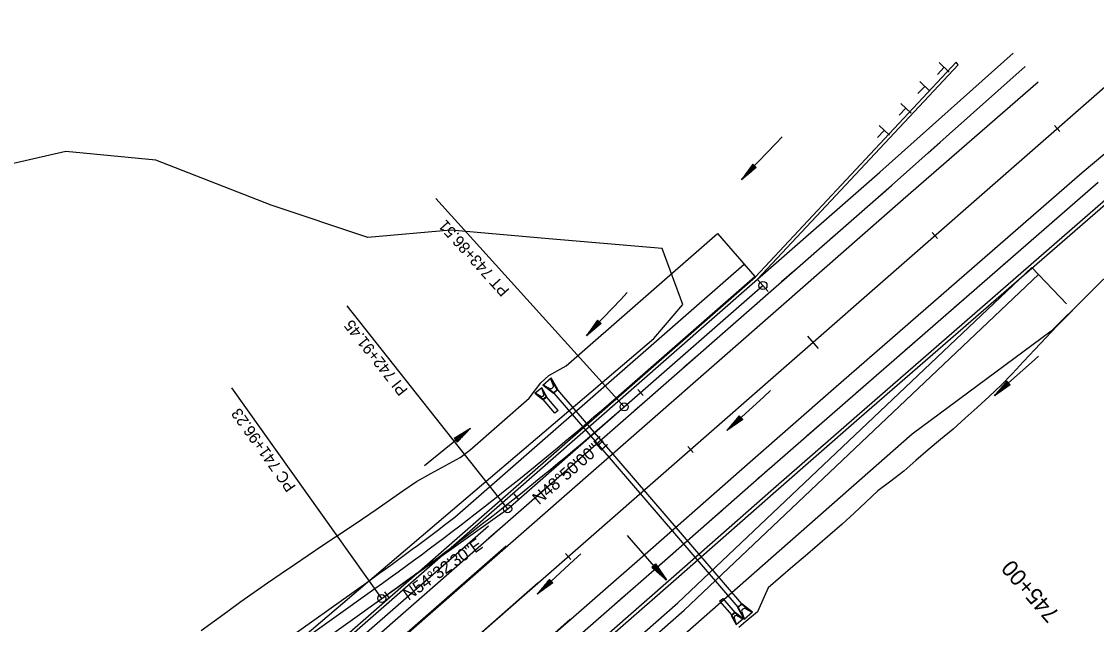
# Model space of a CAD drawing. Extents: x 1300404 to 1323571, y 234004 to 252077.
# Drawn here: x 1312081 to 1312743, y 242384 to 242755 of the extents above; entities that cross this region are included whole.
import ezdxf

# ---------------------------------------------------------------- set-up
doc = ezdxf.new("R2010")
doc.units = 0
for name, color, linetype in [('R_Barrel', 7, 'Continuous'), ('R_Const Limits', 7, 'Continuous'), ('R_Draft', 7, 'Continuous'), ('R_FES', 7, 'Continuous'), ('R_Flooplain', 7, 'Continuous'), ('R_Flow Arrows', 7, 'Continuous'), ('R_Horz Alg Annot', 7, 'Continuous'), ('R_Horz Alg Annot Leader', 7, 'Continuous'), ('R_Horz Alg Major Ticks', 7, 'Continuous'), ('R_Horz Alg Minor Ticks', 7, 'Continuous'), ('R_Horz Alg Station Annot', 7, 'Continuous'), ('R_Horz Alg Tangents', 7, 'Continuous'), ('R_Horz Alg Tangents Text', 7, 'Continuous'), ('R_Lane Edge', 7, 'Continuous'), ('R_Pipe Culvert', 7, 'Continuous'), ('R_Proposed', 7, 'Continuous'), ('R_Shoulder', 7, 'Continuous'), ('R_Temp Barrier Wall', 7, 'Continuous'), ('R_Temp Travel Lane', 7, 'Continuous'), ('R_Temp Travel Stripe', 7, 'Continuous')]:
    doc.layers.add(name, color=color, linetype=linetype)

msp = doc.modelspace()

# ---------------------------------------------------------------- linework, layer by layer
at = {"layer": 'R_Barrel'}
for p, q in [((1312648.96, 242726.58), (1312644.8, 242722.26)), ((1312645.87, 242729.55), (1312652.07, 242723.59)), ((1312636.94, 242714.85), (1312632.78, 242710.53)), ((1312633.85, 242717.82), (1312640.05, 242711.85)), ((1312625.4, 242701.39), (1312621.24, 242697.07)), ((1312622.31, 242704.36), (1312628.51, 242698.39)), ((1312612.04, 242687.8), (1312607.88, 242683.48)), ((1312608.96, 242690.77), (1312615.16, 242684.8))]:
    msp.add_line(p, q, dxfattribs=at)
at = {"layer": 'R_Const Limits'}
for p, q in [((1312416.15, 242542.82), (1312509.35, 242624.32)), ((1312509.35, 242624.32), (1312532.39, 242597.97)), ((1312509.35, 242624.32), (1312532.39, 242597.97)), ((1312724.16, 242581), (1312702.84, 242603.5)), ((1312724.16, 242581), (1312702.84, 242603.5)), ((1312405.62, 242536.92), (1312416.15, 242542.82)), ((1312400.61, 242532.53), (1312405.62, 242536.92)), ((1312393.42, 242522.95), (1312400.61, 242532.53)), ((1312356.89, 242491), (1312393.42, 242522.95))]:
    msp.add_line(p, q, dxfattribs=at)
for points in [[(1312727.96, 242576.99), (1312718.46, 242567.48), (1312711.52, 242560.23), (1312704.65, 242552.9), (1312697.81, 242545.52), (1312690.96, 242538.17), (1312683.93, 242531.01), (1312676.67, 242524.13), (1312669.32, 242517.34), (1312661.88, 242510.66), (1312654.39, 242504.03), (1312646.73, 242497.6), (1312639.1, 242491.13), (1312631.52, 242484.61), (1312623.99, 242478.02), (1312616.06, 242471.9), (1312607.99, 242465.94), (1312600.72, 242459.07), (1312593.47, 242452.16), (1312586.08, 242445.42), (1312578.49, 242438.92), (1312570.91, 242432.39), (1312563.35, 242425.84), (1312555.75, 242419.34), (1312548.13, 242412.87), (1312540.54, 242406.35), (1312540.54, 242406.35), (1312533.94, 242391.51), (1312526.73, 242385.56), (1312522.45, 242381.96)], [(1312191.55, 242380.1), (1312199.69, 242385.98), (1312207.81, 242391.89), (1312215.93, 242397.8), (1312224.09, 242403.66), (1312232.4, 242409.34), (1312240.65, 242415.1), (1312249.02, 242420.72), (1312257.34, 242426.4), (1312265.68, 242432.06), (1312274.12, 242437.59), (1312282.51, 242443.19), (1312290.85, 242448.84), (1312299.17, 242454.52), (1312307.48, 242460.2), (1312315.72, 242465.98), (1312324.03, 242471.66), (1312332.93, 242476.67), (1312341.95, 242481.55), (1312350.86, 242486.56), (1312356.89, 242491)]]:
    msp.add_lwpolyline(points, dxfattribs=at)
at = {"layer": 'R_Draft'}
for p, q in [((1308396.96, 238971.92), (1312368.36, 242444.53)), ((1308407.83, 238959.5), (1312379.22, 242432.11)), ((1308447.32, 238914.33), (1312418.71, 242386.94))]:
    msp.add_line(p, q, dxfattribs=at)
at = {"layer": 'R_FES'}
for p, q in [((1312401.86, 242531.06), (1312406.88, 242535.46)), ((1312408.21, 242531.11), (1312406.62, 242535.23)), ((1312410.71, 242528.38), (1312406.62, 242535.23)), ((1312411.12, 242528.35), (1312406.88, 242535.46)), ((1312406.88, 242535.46), (1312408.21, 242531.11)), ((1312401.24, 242529.44), (1312396.97, 242525.85)), ((1312401.01, 242529.25), (1312402.47, 242525.49)), ((1312403.88, 242523.98), (1312401.01, 242529.25)), ((1312404.24, 242523.93), (1312401.24, 242529.44)), ((1312402.47, 242525.49), (1312401.24, 242529.44)), ((1312408.36, 242525.93), (1312401.86, 242531.06)), ((1312406.03, 242528.95), (1312401.86, 242531.06)), ((1312402.12, 242531.29), (1312406.03, 242528.95)), ((1312408.39, 242526.33), (1312402.12, 242531.29)), ((1312411.12, 242528.35), (1312408.36, 242525.93)), ((1312410.71, 242528.38), (1312408.39, 242526.33)), ((1312410.71, 242528.38), (1312411.12, 242528.35)), ((1312401.88, 242521.95), (1312396.97, 242525.85)), ((1312396.97, 242525.85), (1312400.62, 242524.12)), ((1312400.62, 242524.12), (1312397.19, 242526.04)), ((1312401.89, 242522.31), (1312397.19, 242526.04)), ((1312401.88, 242521.95), (1312404.24, 242523.93)), ((1312401.89, 242522.31), (1312401.88, 242521.95)), ((1312401.89, 242522.31), (1312403.88, 242523.98)), ((1312403.88, 242523.98), (1312404.24, 242523.93)), ((1312408.39, 242526.33), (1312408.36, 242525.93)), ((1312524.36, 242396.6), (1312521.59, 242394.19)), ((1312524.33, 242396.2), (1312522, 242394.16)), ((1312524.33, 242396.2), (1312524.36, 242396.6)), ((1312524.33, 242396.2), (1312530.59, 242391.23)), ((1312524.36, 242396.6), (1312530.84, 242391.45)), ((1312520.23, 242391.31), (1312517.87, 242389.32)), ((1312517.87, 242389.32), (1312520.87, 242383.81)), ((1312518.23, 242389.27), (1312517.87, 242389.32)), ((1312520.22, 242390.94), (1312518.23, 242389.27)), ((1312518.23, 242389.27), (1312521.1, 242384)), ((1312520.22, 242390.94), (1312520.23, 242391.31)), ((1312520.22, 242390.94), (1312524.92, 242387.21)), ((1312520.23, 242391.31), (1312525.15, 242387.41)), ((1312521.49, 242389.13), (1312524.92, 242387.21)), ((1312525.15, 242387.41), (1312521.49, 242389.13)), ((1312521.59, 242394.19), (1312525.82, 242387.07)), ((1312522, 242394.16), (1312521.59, 242394.19)), ((1312522, 242394.16), (1312526.08, 242387.29)), ((1312524.28, 242391.48), (1312525.82, 242387.07)), ((1312526.08, 242387.29), (1312524.28, 242391.48)), ((1312525.82, 242387.07), (1312530.84, 242391.45)), ((1312526.71, 242393.35), (1312530.59, 242391.23)), ((1312530.84, 242391.45), (1312526.71, 242393.35)), ((1312519.64, 242387.76), (1312520.87, 242383.81)), ((1312521.1, 242384), (1312519.64, 242387.76)), ((1312520.87, 242383.81), (1312525.15, 242387.41))]:
    msp.add_line(p, q, dxfattribs=at)
for centre, radius, start, end in [((1312406.66, 242530.5), 1.67, 247.94997, 21.48071), ((1312401.25, 242525.2), 1.25, 239.82319, 13.35393), ((1312520.86, 242388.05), 1.25, 59.82319, 193.35393), ((1312525.9, 242391.9), 1.67, 60.89676, 194.4275)]:
    msp.add_arc(centre, radius, start, end, dxfattribs=at)
at = {"layer": 'R_Flooplain'}
for p, q in [((1312108.08, 242674.72), (1312046.9, 242660.87)), ((1312163.47, 242669.51), (1312108.08, 242674.72)), ((1312234.67, 242641.73), (1312163.47, 242669.51)), ((1312294.17, 242621.8), (1312234.67, 242641.73)), ((1312345.21, 242626.48), (1312294.17, 242621.8)), ((1312405.43, 242621.03), (1312345.21, 242626.48)), ((1312475.3, 242615.09), (1312405.43, 242621.03)), ((1312488.09, 242580.57), (1312475.3, 242615.09)), ((1312768.17, 242617.27), (1312714.72, 242564.31)), ((1312470.12, 242559.7), (1312488.09, 242580.57)), ((1312714.72, 242564.31), (1312629.3, 242500.87)), ((1311459.52, 241700.85), (1312470.12, 242559.7)), ((1312629.3, 242500.87), (1311599.52, 241597.01))]:
    msp.add_line(p, q, dxfattribs=at)
at = {"layer": 'R_Flow Arrows'}
for p, q in [((1312531.03, 242667.02), (1312524.1, 242657.41)), ((1312533.25, 242664.94), (1312531.03, 242667.02)), ((1312533.25, 242664.94), (1312524.1, 242657.41)), ((1312435.53, 242571.07), (1312428.61, 242561.46)), ((1312437.75, 242568.99), (1312428.61, 242561.46)), ((1312437.75, 242568.99), (1312435.53, 242571.07)), ((1312687.52, 242533.5), (1312679.81, 242524.51)), ((1312689.56, 242531.24), (1312679.81, 242524.51)), ((1312689.56, 242531.24), (1312687.52, 242533.5)), ((1312522.8, 242512.19), (1312515.18, 242503.12)), ((1312524.86, 242509.95), (1312515.18, 242503.12)), ((1312524.86, 242509.95), (1312522.8, 242512.19)), ((1312347.19, 242498.31), (1312357.24, 242504.6)), ((1312349.12, 242495.96), (1312357.24, 242504.6)), ((1312347.19, 242498.31), (1312349.12, 242495.96)), ((1312471.16, 242420.97), (1312468.9, 242418.94)), ((1312468.9, 242418.94), (1312477.88, 242411.21)), ((1312471.16, 242420.97), (1312477.88, 242411.21)), ((1312405.97, 242411.53), (1312398.34, 242402.47)), ((1312408.03, 242409.29), (1312398.34, 242402.47)), ((1312408.03, 242409.29), (1312405.97, 242411.53))]:
    msp.add_line(p, q, dxfattribs=at)
for points in [[(1312549.22, 242683.88), (1312545.24, 242679.71), (1312524, 242657.51)], [(1312531.47, 242666.6), (1312528.26, 242663.17)], [(1312531.25, 242666.81), (1312529.64, 242665.1)], [(1312531.92, 242666.19), (1312527.66, 242661.65), (1312525.48, 242659.34)], [(1312532.36, 242665.77), (1312528.11, 242661.24), (1312525.93, 242658.92)], [(1312531.69, 242666.4), (1312527.44, 242661.86), (1312526.87, 242661.26)], [(1312532.58, 242665.56), (1312528.33, 242661.03), (1312527.76, 242660.42)], [(1312532.8, 242665.36), (1312529.59, 242661.93)], [(1312533.03, 242665.15), (1312531.42, 242663.43)], [(1312453.72, 242587.93), (1312449.75, 242583.76), (1312428.5, 242561.56)], [(1312436.42, 242570.24), (1312432.17, 242565.7), (1312429.99, 242563.39)], [(1312436.87, 242569.82), (1312432.61, 242565.29), (1312430.43, 242562.97)], [(1312436.2, 242570.45), (1312431.95, 242565.91), (1312431.38, 242565.31)], [(1312437.09, 242569.62), (1312432.84, 242565.08), (1312432.26, 242564.47)], [(1312435.98, 242570.66), (1312432.76, 242567.23)], [(1312437.31, 242569.41), (1312434.1, 242565.98)], [(1312435.76, 242570.86), (1312434.15, 242569.15)], [(1312437.53, 242569.2), (1312435.92, 242567.48)], [(1312707.06, 242548.78), (1312702.75, 242544.95), (1312679.72, 242524.62)], [(1312542.05, 242527.81), (1312537.81, 242523.9), (1312515.18, 242503.13)], [(1312688.34, 242532.6), (1312683.72, 242528.44), (1312681.35, 242526.31)], [(1312688.75, 242532.15), (1312684.13, 242527.98), (1312681.76, 242525.86)], [(1312688.13, 242532.82), (1312683.52, 242528.66), (1312682.9, 242528.11)], [(1312688.95, 242531.92), (1312684.33, 242527.76), (1312683.71, 242527.2)], [(1312687.93, 242533.05), (1312684.44, 242529.9)], [(1312689.15, 242531.7), (1312685.66, 242528.55)], [(1312687.73, 242533.28), (1312685.98, 242531.7)], [(1312689.36, 242531.47), (1312687.61, 242529.9)], [(1312523.63, 242511.29), (1312519.05, 242507.09), (1312516.7, 242504.95)], [(1312524.04, 242510.85), (1312519.46, 242506.64), (1312517.11, 242504.5)], [(1312523.42, 242511.52), (1312518.84, 242507.31), (1312518.23, 242506.75)], [(1312524.24, 242510.62), (1312519.66, 242506.42), (1312519.05, 242505.85)], [(1312523.22, 242511.74), (1312519.75, 242508.56)], [(1312524.45, 242510.4), (1312520.99, 242507.22)], [(1312523.01, 242511.97), (1312521.28, 242510.38)], [(1312524.65, 242510.17), (1312522.92, 242508.58)], [(1312328.9, 242481.6), (1312333.39, 242485.23), (1312357.33, 242504.48)], [(1312347.77, 242497.61), (1312352.58, 242501.56), (1312353.22, 242502.08)], [(1312347.97, 242497.37), (1312352.77, 242501.32), (1312355.24, 242503.33)], [(1312348.35, 242496.9), (1312353.16, 242500.85), (1312355.62, 242502.86)], [(1312348.55, 242496.67), (1312353.35, 242500.61), (1312353.99, 242501.14)], [(1312347.39, 242498.08), (1312349.2, 242499.57)], [(1312347.58, 242497.84), (1312351.21, 242500.83)], [(1312348.74, 242496.43), (1312352.37, 242499.42)], [(1312348.93, 242496.2), (1312350.75, 242497.69)], [(1312453.67, 242438.51), (1312457.49, 242434.19), (1312477.77, 242411.11)], [(1312425.22, 242427.15), (1312420.98, 242423.24), (1312398.35, 242402.47)], [(1312469.13, 242419.14), (1312470.7, 242417.39)], [(1312469.35, 242419.34), (1312472.49, 242415.84)], [(1312469.58, 242419.55), (1312473.73, 242414.92), (1312474.28, 242414.3)], [(1312469.81, 242419.75), (1312473.96, 242415.12), (1312476.07, 242412.75)], [(1312470.26, 242420.16), (1312474.41, 242415.53), (1312476.53, 242413.15)], [(1312470.48, 242420.36), (1312474.64, 242415.73), (1312475.19, 242415.11)], [(1312470.71, 242420.56), (1312473.85, 242417.06)], [(1312470.94, 242420.76), (1312472.51, 242419.02)], [(1312406.8, 242410.63), (1312402.21, 242406.43), (1312399.87, 242404.29)], [(1312407.21, 242410.19), (1312402.63, 242405.98), (1312400.28, 242403.84)], [(1312406.59, 242410.86), (1312402.01, 242406.66), (1312401.4, 242406.09)], [(1312407.41, 242409.96), (1312402.83, 242405.76), (1312402.22, 242405.2)], [(1312406.38, 242411.08), (1312402.92, 242407.9)], [(1312407.62, 242409.74), (1312404.15, 242406.56)], [(1312406.18, 242411.31), (1312404.45, 242409.72)], [(1312407.82, 242409.51), (1312406.09, 242407.93)]]:
    msp.add_lwpolyline(points, dxfattribs=at)
at = {"layer": 'R_Horz Alg Annot Leader'}
for points in [[(1312451.89, 242517.62), (1312335.87, 242645.95)], [(1312451.89, 242517.62), (1312335.87, 242645.95)], [(1312378.37, 242457.27), (1312281.46, 242579.92)], [(1312378.37, 242457.27), (1312281.46, 242579.92)], [(1312302.65, 242399.71), (1312210.36, 242529.29)], [(1312302.65, 242399.71), (1312210.36, 242529.29)], [(1312380.21, 242454.94), (1312379.13, 242456.31)], [(1312380.21, 242454.94), (1312379.13, 242456.31)]]:
    msp.add_lwpolyline(points, dxfattribs=at)
at = {"layer": 'R_Horz Alg Major Ticks'}
for points in [[(1312534.04, 242596.09), (1312540.62, 242588.56)], [(1312534.04, 242596.09), (1312540.62, 242588.56)], [(1312564.67, 242561.06), (1312571.25, 242553.53)], [(1312564.67, 242561.06), (1312571.25, 242553.53)]]:
    msp.add_lwpolyline(points, dxfattribs=at)
at = {"layer": 'R_Horz Alg Minor Ticks'}
for points in [[(1312716.88, 242690.83), (1312720.17, 242687.06)], [(1312716.88, 242690.83), (1312720.17, 242687.06)], [(1312641.6, 242625), (1312644.89, 242621.24)], [(1312641.6, 242625), (1312644.89, 242621.24)], [(1312460.4, 242528.38), (1312463.69, 242524.62)], [(1312460.4, 242528.38), (1312463.69, 242524.62)], [(1312491.04, 242493.35), (1312494.33, 242489.59)], [(1312491.04, 242493.35), (1312494.33, 242489.59)], [(1312383.94, 242464.12), (1312387.06, 242460.22)], [(1312383.94, 242464.12), (1312387.06, 242460.22)], [(1312415.76, 242427.53), (1312419.05, 242423.76)], [(1312415.76, 242427.53), (1312419.05, 242423.76)], [(1312304.27, 242403.93), (1312307.18, 242399.86)], [(1312304.27, 242403.93), (1312307.18, 242399.86)]]:
    msp.add_lwpolyline(points, dxfattribs=at)
at = {"layer": 'R_Horz Alg Tangents'}
for p, q in [((1312380.21, 242454.94), (1312451.89, 242517.62)), ((1312380.21, 242454.94), (1312451.89, 242517.62)), ((1312302.65, 242399.71), (1312380.21, 242454.94)), ((1312302.65, 242399.71), (1312380.21, 242454.94))]:
    msp.add_line(p, q, dxfattribs=at)
at = {"layer": 'R_Lane Edge'}
for p, q in [((1312484.9, 242396.99), (1312702.84, 242603.5)), ((1312446.95, 242523.27), (1312532.39, 242597.97)), ((1311865.98, 242097.91), (1312298.3, 242405.81)), ((1312070.61, 242034.74), (1312484.9, 242396.99))]:
    msp.add_line(p, q, dxfattribs=at)
msp.add_arc((1311194.72, 243955.36), 1902.36, 305.45833, 311.16667, dxfattribs=at)
at = {"layer": 'R_Pipe Culvert'}
for p, q in [((1312410.87, 242528.13), (1312524.11, 242396.39)), ((1312409.19, 242513.84), (1312402.1, 242522.13)), ((1312411.21, 242515.32), (1312404.01, 242523.74)), ((1312408.61, 242526.15), (1312521.85, 242394.41)), ((1312411.21, 242515.32), (1312409.19, 242513.84)), ((1312510.68, 242398.19), (1312512.7, 242399.67)), ((1312510.68, 242398.19), (1312518.1, 242389.51)), ((1312512.7, 242399.67), (1312520.01, 242391.12))]:
    msp.add_line(p, q, dxfattribs=at)
at = {"layer": 'R_Proposed'}
for p, q in [((1308427.57, 238936.91), (1312793.8, 242754.77)), ((1308427.57, 238936.91), (1312793.8, 242754.77)), ((1312451.89, 242517.62), (1312537.33, 242592.33)), ((1312451.89, 242517.62), (1312537.33, 242592.33)), ((1309180.37, 239595.16), (1312398.96, 242409.52)), ((1309180.37, 239595.16), (1312398.96, 242409.52)), ((1311870.33, 242091.8), (1312302.65, 242399.71)), ((1311870.33, 242091.8), (1312302.65, 242399.71))]:
    msp.add_line(p, q, dxfattribs=at)
for centre in [(1312537.33, 242592.33), (1312537.33, 242592.33), (1312451.89, 242517.62), (1312451.89, 242517.62), (1312380.21, 242454.94), (1312380.21, 242454.94), (1312302.65, 242399.71), (1312302.65, 242399.71)]:
    msp.add_circle(centre, 2.5, dxfattribs=at)
msp.add_arc((1311194.72, 243955.36), 1909.86, 305.45833, 311.16667, dxfattribs=at)
msp.add_arc((1311194.72, 243955.36), 1909.86, 305.45833, 311.16667, dxfattribs=at)
at = {"layer": 'R_Shoulder'}
for p, q in [((1312347.7, 242449.76), (1312525.81, 242605.5)), ((1312488.94, 242392.56), (1312706.97, 242599.15)), ((1311862.49, 242102.8), (1312294.82, 242410.7)), ((1312074.56, 242030.22), (1312488.94, 242392.56))]:
    msp.add_line(p, q, dxfattribs=at)
msp.add_arc((1311194.72, 243955.36), 1896.36, 305.45833, 307.4446, dxfattribs=at)
at = {"layer": 'R_Temp Barrier Wall'}
for p, q in [((1312532.68, 242597.64), (1312656.29, 242729.72)), ((1312533.99, 242596.14), (1312657.61, 242728.21)), ((1312657.61, 242728.21), (1312656.29, 242729.72)), ((1311892.96, 242037.93), (1312532.68, 242597.64))]:
    msp.add_line(p, q, dxfattribs=at)
for points in [[(1312162.13, 242133.19), (1312208.15, 242173.4), (1312269.24, 242227.03), (1312376.43, 242320.64), (1312482.53, 242413.42), (1312543.91, 242467.34), (1312595.2, 242512.14), (1312748.29, 242645.21), (1312753.15, 242649.34)], [(1312163.45, 242131.69), (1312209.47, 242171.9), (1312270.56, 242225.52), (1312377.74, 242319.14), (1312483.84, 242411.92), (1312545.23, 242465.84), (1312596.52, 242510.63), (1312749.59, 242643.69), (1312754.47, 242647.84)]]:
    msp.add_lwpolyline(points, dxfattribs=at)
at = {"layer": 'R_Temp Travel Lane'}
msp.add_lwpolyline([(1312147.66, 242149.76), (1312193.66, 242189.95), (1312254.75, 242243.58), (1312361.95, 242337.21), (1312468.02, 242429.96), (1312529.42, 242483.89), (1312580.75, 242528.73), (1312733.95, 242661.89), (1312822.72, 242736.25)], dxfattribs=at)
at = {"layer": 'R_Temp Travel Stripe'}
for p, q in [((1312609.25, 242661.98), (1312691.36, 242735.2)), ((1312698.68, 242726.99), (1312616.58, 242653.77)), ((1312623.74, 242645.43), (1312706.79, 242717.56)), ((1312533.99, 242596.14), (1312609.25, 242661.98)), ((1312616.5, 242653.71), (1311826.26, 241962.3)), ((1312548.48, 242579.58), (1312623.74, 242645.43)), ((1311894.27, 242036.42), (1312533.99, 242596.14)), ((1311908.76, 242019.86), (1312548.48, 242579.58))]:
    msp.add_line(p, q, dxfattribs=at)
for points in [[(1312676.29, 242707.02), (1312668.82, 242700.37)], [(1312646.43, 242680.4), (1312638.97, 242673.74)], [(1312154.9, 242141.47), (1312200.9, 242181.68), (1312262, 242235.3), (1312369.19, 242328.93), (1312475.28, 242421.69), (1312536.66, 242475.62), (1312587.98, 242520.43), (1312743.82, 242655.9)], [(1312616.58, 242653.78), (1312616.58, 242653.77), (1312616.5, 242653.71), (1312609.05, 242647.19)], [(1312715.5, 242631.28), (1312723.05, 242637.85)], [(1312586.47, 242627.44), (1312578.95, 242620.85)], [(1312685.31, 242605.04), (1312692.86, 242611.6)], [(1312556.37, 242601.1), (1312548.84, 242594.51)], [(1312655.12, 242578.8), (1312662.67, 242585.36)], [(1312526.26, 242574.76), (1312518.74, 242568.17)], [(1312624.93, 242552.56), (1312632.48, 242559.12)], [(1312496.16, 242548.42), (1312488.63, 242541.83)], [(1312594.74, 242526.31), (1312602.29, 242532.88)], [(1312466.05, 242522.08), (1312458.53, 242515.49)], [(1312564.6, 242500.02), (1312572.13, 242506.6)], [(1312435.95, 242495.74), (1312428.42, 242489.15)], [(1312534.48, 242473.7), (1312536.66, 242475.62), (1312542.01, 242480.28)], [(1312405.84, 242469.4), (1312398.32, 242462.81)], [(1312504.43, 242447.3), (1312511.94, 242453.9)], [(1312375.74, 242443.06), (1312368.21, 242436.47)], [(1312474.37, 242420.9), (1312475.28, 242421.69), (1312481.89, 242427.5)], [(1312345.63, 242416.72), (1312338.11, 242410.13)], [(1312444.26, 242394.57), (1312451.79, 242401.15)], [(1312315.53, 242390.38), (1312308, 242383.79)]]:
    msp.add_lwpolyline(points, dxfattribs=at)

# ---------------------------------------------------------------- texts
at = {"layer": 'R_Horz Alg Annot'}
for s, rotation, p in [('PT 743+86.51', 132.11685, (1312381.74, 242589.54)), ('PI 742+91.45', 128.3125, (1312319.1, 242528.05)), ('PI 742+91.45', 128.3125, (1312319.1, 242528.05)), ('PC 741+96.23', 125.45833, (1312250.07, 242468.56)), ('PC 741+96.23', 125.45833, (1312250.07, 242468.56))]:
    msp.add_text(s, height=7, rotation=rotation, dxfattribs=at).set_placement(p)
at = {"layer": 'R_Horz Alg Station Annot'}
msp.add_text('745+00', height=10, rotation=131.16667, dxfattribs=at).set_placement((1312720.47, 242390.48))
msp.add_text('745+00', height=10, rotation=131.16667, dxfattribs=at).set_placement((1312720.47, 242390.48))
at = {"layer": 'R_Horz Alg Tangents Text'}
for s, rotation, p in [('N48%%d50\'00"E', 41.16667, (1312399.44, 242457.1)), ('N48%%d50\'00"E', 41.16667, (1312399.44, 242457.1)), ('N54%%d32\'30"E', 35.45833, (1312319.13, 242398.23)), ('N54%%d32\'30"E', 35.45833, (1312319.13, 242398.23))]:
    msp.add_text(s, height=7.5, rotation=rotation, dxfattribs=at).set_placement(p)

doc.saveas('drawing.dxf')
